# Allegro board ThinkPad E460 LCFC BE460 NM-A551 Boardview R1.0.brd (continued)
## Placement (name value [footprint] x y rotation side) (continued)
IT1  Test_Point_40MIL  [TPC40]  186.29 137.7 0 top
IT2  Test_Point_40MIL  [TPC40]  181.6 137.74 0 top
IT3  Test_Point_40MIL  [TPC40]  199.03 116.56 0 top
IT4  Test_Point_40MIL  [TPC40]  196.07 132.24 0 top
IT5  Test_Point_40MIL  [TPC40]  201.15 120.81 0 top
IT6  Test_Point_40MIL  [TPC40]  194.56 112.7 0 top
IT7  Test_Point_40MIL  [TPC40]  193.03 112.7 0 top
IT8  Test_Point_40MIL  [TPC40]  172.32 123.86 0 top
J1  SHORT PADS  [SHORTPADS]  267.95 149.19 0 top
J5  -  [JUMP_43X118]  221.34 133.04 270 top
J6  -  [JUMP_43X118]  215.37 133.04 270 top
JBATT1  FOX_GS73071-10272-M-7H  [FOX_GS73071-10272-M-7H_7P-T]  255.2 122.55 0 bottom
JC1  -  [JUMP_43X79]  144.02 158.5 0 top
JC2  -  [JUMP_43X118]  88.87 148.48 90 top
JCMOS1  SHORT PADS  [SHORTPADS]  126.61 138.1 0 bottom
JCP  ACES_50506-01201-AT1  [ACES_50506-01201-AT1_12P]  117.66 62.9 180 top
JCR  ACES_51530-01401-W01  [ACES_51530-01401-W01_14P-T]  164.45 54.72 0 top
JDIMM1  LCN_DAN06-K4406-0102  [LCN_DAN06-K4406-0102_204P]  163.55 90.35 90 bottom
JDIMM2  LCN_DAN06-K4406-0103  [LCN_DAN06-K4406-0103_204P]  150.35 90.35 270 bottom
JFAN  DRAPH_WS32050-S0471-HF  [DRAPH_WS32050-S0471-HF_5P-T]  46.2 48.31 180 bottom
JFPB  ACES_88514-0060N-071  [ACES_88514-0060N-071_6P-T]  175.96 76.54 180 top
JHDD  HIGHS_SA2S0226-3201H  [HIGHS_SA2S0226-3201H_22P]  225.57 75.7 180 bottom
JHDMI  CONCR_099ATAC19NBLCNF  [CONCR_099ATAC19NBLCNF_19P]  289.85 62 270 bottom
JKB  JAE_FL10F032HA2R3000  [JAE_FL10F032HA2R3000_32P]  147.2 71.75 0 top
JLCD  I-PEX_20525-030E-02  [I-PEX_20525-030E-02_30P-T]  58.36 112.46 315 top
JLINK  DRAPH_PJSS0296-MB21H  [DRAPH_PJSS0296-MB21H_29P-T]  285.3 121.47 90 bottom
JLOGO  TE_2041180-2  [TE_2041180-2_2P-T]  280.79 24.59 180 top
JME1  SHORT PADS  [SHORTPADS]  126.61 136.83 0 bottom
JRJ451  SINGA_2RJ3089-108211F  [SINGA_2RJ3089-108211F_12P]  288.38 82.57 90 bottom
JRTC  TE_2041180-2  [TE_2041180-2_2P-T]  234.32 170.1 0 bottom
JSPK  TYCO_2041180-4  [TYCO_2041180-4_4P-T]  240.28 98.4 0 bottom
JTOUCH1  ACES_50463-0104A-P01  [ACES_50463-0104A-P01_10P-T]  251.5 155.63 0 top
JTP  JAE_FL10F012HA1R3000  [JAE_FL10F012HA1R3000_12P]  147.2 60.75 180 top
JU3AC  HIGHS_FC5AF261-1151H  [HIGHS_FC5AF261-1151H_26P]  128.66 56.61 180 top
JUSB1  SUYIN_020053GR009M283ZL  [SUYIN_020053GR009M283ZL_9P]  285.59 29.5 270 bottom
JUSB2  SUYIN_020053GR009M283ZL  [SUYIN_020053GR009M283ZL_9P]  285.59 7.5 270 bottom
JV1  -  [JUMP_43X79]  49.87 127.18 0 bottom
JV3  -  [JUMP_43X39]  71.13 161.58 180 top
JWLBT  TE_2199230-8  [TE_2199230-8_75P]  268.95 162.77 180 bottom
L1  EXC24CH900U_4P  [PANAS_EXC24CH900U_4P]  281.17 58.85 270 top
L2  EXC24CH900U_4P  [PANAS_EXC24CH900U_4P]  282.44 60.75 270 top
L3  EXC24CH900U_4P  [PANAS_EXC24CH900U_4P]  282.31 62.78 270 top
L4  EXC24CH900U_4P  [PANAS_EXC24CH900U_4P]  281.17 57.07 270 top
L5  EXC24CH900U_4P  [PANAS_EXC24CH900U_4P]  59.43 125.52 315 bottom
L6  EXC24CH900U_4P  [PANAS_EXC24CH900U_4P]  137.28 64.05 180 top
L9  EXC24CH900U_4P  [PANAS_EXC24CH900U_4P]  280.03 33.07 90 bottom
L10  EXC24CH900U_4P  [PANAS_EXC24CH900U_4P]  280.03 34.84 90 bottom
L11  EXC24CH900U_4P  [PANAS_EXC24CH900U_4P]  283.2 41.19 180 top
L12  EXC24CH900U_4P  [PANAS_EXC24CH900U_4P]  279.9 13.76 90 bottom
L13  EXC24CH900U_4P  [PANAS_EXC24CH900U_4P]  279.9 15.41 90 bottom
L14  EXC24CH900U_4P  [PANAS_EXC24CH900U_4P]  278.76 12.62 270 top
L15  EXC24CH900U_4P  [PANAS_EXC24CH900U_4P]  277.74 116.63 270 top
L16  EXC24CH900U_4P  [PANAS_EXC24CH900U_4P]  274.69 115.11 270 top
L17  EXC24CH900U_4P  [PANAS_EXC24CH900U_4P]  135.63 63.8 180 top
L18  EXC24CH900U_4P  [PANAS_EXC24CH900U_4P]  130.24 62.94 270 top
L19  EXC24CH900U_4P  [PANAS_EXC24CH900U_4P]  242.18 153.59 180 top
L20  EXC24CH900U_4P  [PANAS_EXC24CH900U_4P]  274.19 122.47 180 top
LC1  0_0805_5%  [R0805_SHORT]  84.55 130.55 90 top
LC2  0_0805_5%  [R0805_SHORT]  109.34 133.23 270 top
LC3  0_0805_5%  [R0805_SHORT]  83.61 131.57 0 bottom
LC4  0_0805_5%  [R0805_SHORT]  82.76 126.03 0 top
LC5  0_0805_5%  [R0805_SHORT]  82.76 128.06 0 top
LE1  BLM18PG121SN1D_2P  [MURAT_BLM18PG121SN1D_2P]  199.84 119.54 180 top
LE2  BLM18PG121SN1D_2P  [MURAT_BLM18PG121SN1D_2P]  198.64 120.81 0 top
LL1  4.7UH_FLF3215T-4R7M_20%  [TDK_FLF3215T-4R7M_2P]  254.16 87.28 0 bottom
LV3  BLM18PG221SN1D_2P  [MURAT_BLM18PG221SN1D_2P]  43.82 173.2 270 bottom
LV4  BLM18PG121SN1D_2P  [MURAT_BLM18PG121SN1D_2P]  42.65 170.69 270 top
LV5  BLM18PG121SN1D_2P  [MURAT_BLM18PG121SN1D_2P]  50.25 130.54 90 bottom
NOREF  -  []  192.07 77.63 0 top
NOREF#2  -  []  180.04 3.42 0 top
NOREF#3  -  []  212.11 124.71 0 top
NOREF#4  -  [unnamed#2]  10.79 131.08 0 top
NOREF#5  -  []  192.93 114.91 0 top
NOREF#6  -  []  211.37 84.37 0 top
NOREF#7  -  []  90.74 54.21 0 top
NOREF#8  -  []  160.53 61.96 180 bottom
NOREF#9  -  []  154.83 60.22 180 bottom
NOREF#10  -  []  124.57 61.42 180 bottom
PC1  1U_0603_25V7K  [C_0603]  240.47 129.17 180 bottom
PC2  680P_0402_50V7-K  [C_0402]  276.64 107.78 90 top
PC3  0.1U_0402_6.3V  [C_0402]  275.72 107.78 90 top
PC4  1000P_0402_50V7-K  [C_0402]  278.11 107.8 90 bottom
PC5  100P_0402_50V8-J  [C_0402]  279.03 107.8 90 bottom
PC6  100P_0402_50V8J  [C_0402]  275.77 102.39 270 bottom
PC7  1000P_0402_50V7-K  [C_0402]  274.89 102.39 270 bottom
PC8  0.1U_0603_16V7K  [C_0603]  222.21 169.63 270 top
PC9  1000P_0402_50V  [C_0402]  264.84 109.52 0 bottom
PC10  0.01U_0402_25V  [C_0402]  260.28 109.25 180 bottom
PC101  470P_0402_50V  [C_0402]  273.95 108.77 180 bottom
PC102  0.022U_0402_25V  [C_0402]  272.42 103.64 180 bottom
PC103  10U_0805_25V6-K  [C_0805]  265.56 102.27 0 bottom
PC104  10U_0805_25V6-K  [C_0805]  263.76 102.22 180 bottom
PC105  0.1U_0402_25V7K  [C_0402]  222.1 105.32 180 bottom
PC106  0.1U_0402_25V7K  [C_0402]  223 104.82 0 bottom
PC107  1U_0603_25V7-K  [C_0603]  221.29 104.02 180 bottom
PC108  0.01U_0603_50V7K  [C_0603]  247.71 101.51 0 top
PC109  100P_0402_50V8-J  [C_0402]  223.86 107.09 270 bottom
PC110  2200P_0402_25V7-K  [C_0402]  233.05 119.29 180 bottom
PC111  47P_0402_50V8-J  [C_0402]  232.14 120.17 0 bottom
PC112  68P_0402_50V8-J  [C_0402]  232.14 121.04 0 bottom
PC113  10U_0805_25V6K  [C_0805]  228.66 118.7 180 bottom
PC114  10U_0805_25V6K  [C_0805]  228.66 120.43 180 bottom
PC115  1U_0603_25V  [C_0603]  222.84 108.92 0 bottom
PC116  4.7U_0603_10V6-M  [C_0603]  224.06 112.53 0 bottom
PC117  0.1U_0402_25V7K  [C_0402]  217.02 106.18 90 bottom
PC118  0.047U_0603_25V  [C_0603]  224.31 110.14 0 bottom
PC119  10U_0805_25V6-K  [C_0805]  256.83 102.17 90 bottom
PC120  10U_0805_25V6-K  [C_0805]  254.24 102.19 90 bottom
PC121  680P_0402_50V7K  [C_0402]  234.12 117.18 90 top
PC122  0.1U_0402_25V7K  [C_0402]  221.47 117 270 bottom
PC123  0.1U_0402_25V7K  [C_0402]  218.12 116.97 270 bottom
PC124  0.1U_0402_25V7K  [C_0402]  219.69 117.81 180 bottom
PC125  100P_0402_50V8J  [C_0402]  214.28 105.8 90 bottom
PC126  100P_0402_50V8J  [C_0402]  213.62 109.38 0 bottom
PC127  100P_0402_50V8J  [C_0402]  212.76 109.4 90 bottom
PC128  0.1U_0402_25V6  [C_0402]  223.22 116.44 180 bottom
PC201  0.1U_0402_25V6-K  [C_0402]  210.52 168.1 180 bottom
PC202  10U_0805_25V6-K  [C_0805]  210.5 170.29 180 bottom
PC203  0.1U_0603_25V7-M  [C_0603]  212.07 161.93 90 top
PC204  22U_0805_6.3V6-M  [C_0805]  217.61 155.94 0 bottom
PC205  22U_0805_6.3V6-M  [C_0805]  217.13 154.16 0 bottom
PC206  22U_0805_6.3V6-M  [C_0805]  211.82 152.1 180 bottom
PC207  22U_0805_6.3V6-M  [C_0805]  211.74 154.11 180 bottom
PC208  4.7U_0603_6.3V6-K  [C_0603]  216.57 167.72 0 bottom
PC209  680P_0402_50V7K  [C_0402]  208.64 165.56 270 bottom
PC210  2200P_0402_25V7-K  [C_0402]  217.02 152.79 0 bottom
PC211  0.1U_0402_25V6  [C_0402]  217 151.87 0 bottom
PC212  0.01U_0402_25V7-K  [C_0402]  216.67 165.79 0 bottom
PC213  0.1U_0402_25V6-K  [C_0402]  217.94 164.4 180 bottom
PC214  10U_0805_25V6-K  [C_0805]  198.29 174.09 270 bottom
PC215  0.1U_0402_25V6-K  [C_0402]  199.94 174.67 90 bottom
PC216  10U_0805_25V6-K  [C_0805]  198.29 174.09 270 top
PC217  0.1U_0603_25V7-M  [C_0603]  200.96 167.12 90 top
PC218  1U_0603_25V6M  [C_0603]  205.06 175.35 270 bottom
PC219  22U_0805_6.3V6-M  [C_0805]  203.44 157.74 0 bottom
PC220  22U_0805_6.3V6-M  [C_0805]  203.44 157.74 0 top
PC221  22U_0805_6.3V6-M  [C_0805]  198.56 160.64 180 bottom
PC222  22U_0805_6.3V6-M  [C_0805]  203.44 159.47 0 top
PC223  22U_0805_6.3V6-M  [C_0805]  203.44 159.47 0 bottom
PC224  22U_0805_6.3V6-M  [C_0805]  198.56 160.64 180 top
PC225  4.7U_0603_6.3V6-K  [C_0603]  202.55 175.35 0 bottom
PC226  680P_0402_50V7K  [C_0402]  197.7 168.9 270 bottom
PC227  2200P_0402_25V7-K  [C_0402]  204.38 156.45 0 bottom
PC228  0.1U_0402_25V6  [C_0402]  198.97 159.32 180 bottom
PC229  6800P_0402_25V7-K  [C_0402]  204.38 172.14 270 bottom
PC230  47P_0402_50V8-J  [C_0402]  210.5 168.97 180 bottom
PC231  47P_0402_50V8-J  [C_0402]  200.83 174.67 90 bottom
PC301  10U_0603_6.3V6M  [C_0603]  177.58 169.25 270 top
PC302  10U_0805_25V6-K  [C_0805]  170.95 167.68 270 top
PC303  10U_0805_25V6-K  [C_0805]  171.59 167.55 270 bottom
PC304  0.1U_0402_25V6  [C_0402]  171.16 169.13 90 top
PC305  47P_0402_50V8-J  [C_0402]  169.61 166.9 270 top
PC306  68P_0402_50V8J  [C_0402]  170.23 166.91 270 bottom
PC307  2200P_0402_25V  [C_0402]  171.15 169.14 90 bottom
PC308  10U_0603_6.3V6M  [C_0603]  179.08 167.01 270 top
PC309  0.1U_0402_6.3V7-K  [C_0402]  177.45 166.94 180 top
PC310  0.22U_0603_25V7K  [C_0603]  177.53 173.15 180 top
PC311  330U_D2_2V_R9M  [C_D2]  159.29 166.3 0 bottom
PC312  2200P_0402_25V7-K  [C_0402]  157.8 163.55 270 bottom
PC313  0.1U_0402_25V6  [C_0402]  158.68 163.55 270 bottom
PC314  470P_0402_50V7K  [C_0402]  181.67 165.82 90 top
PC315  0.033U_0402_16V7K  [C_0402]  180.8 166.37 270 top
PC316  1U_0402_10VA-K  [C_0402]  181.13 173.29 0 top
PC317  680P_0402_50V7K  [C_0402]  168.31 175.31 270 top
PC318  0.1U_0402_6.3V7-K  [C_0402]  184.33 168.59 0 top
PC319  0.1U_0402_16V  [C_0402]  184.33 170.36 0 top
PC401  0.01U_0402_25V7-K  [C_0402]  70.06 54.24 270 bottom
PC402  1U_0402_6.3V6-K  [C_0402]  68.13 53.98 0 bottom
PC403  0.1U_0402_6.3V6-K  [C_0402]  55.38 60.81 0 bottom
PC404  1000P_0402_25V7-K  [C_0402]  60.28 51.04 270 bottom
PC405  0.033U_0402_25V7K  [C_0402]  58.58 56.83 270 bottom
PC406  1000P_0402_25V7-K  [C_0402]  59.39 51.85 270 bottom
PC407  3300P_0402_50V7-K  [C_0402]  60.31 51.87 90 bottom
PC408  0.1U_0402_25V6-K  [C_0402]  63.89 51.82 270 bottom
PC409  15P_0402_50V8-J  [C_0402]  58.5 53.65 0 bottom
PC410  1500P_0402_50V7-K  [C_0402]  58.5 52.76 0 bottom
PC411  270P_0402_50V7-M  [C_0402]  57.69 57.74 0 bottom
PC412  1000P_0402_50V7-K  [C_0402]  57.84 55.07 0 bottom
PC413  1000P_0402_25V7-K  [C_0402]  69.53 63.15 180 bottom
PC414  0.1U_0402_25V6-K  [C_0402]  69.91 56.75 90 bottom
PC415  3300P_0402_50V7-K  [C_0402]  69.45 61.88 180 bottom
PC416  470P_0402_50V8-J  [C_0402]  71.66 62.57 180 bottom
PC417  0.1U_0402_16V7-K  [C_0402]  70.9 57.18 270 bottom
PC418  100P_0402_50V7-K  [C_0402]  71.69 58.02 180 top
PC419  1000P_0402_25V7-K  [C_0402]  71.66 58.02 180 bottom
PC420  2200P_0402_25V7-K  [C_0402]  71.63 59.95 180 bottom
PC421  470P_0402_50V8-J  [C_0402]  73.24 60.81 180 bottom
PC422  33P_0402_50V8-J  [C_0402]  70.77 60.81 270 top
PC423  1000P_0402_25V7-K  [C_0402]  68.89 66.12 270 bottom
PC424  0.1U_0402_25V6-K  [C_0402]  70.97 55.3 270 bottom
PC425  1000P_0402_25V7-K  [C_0402]  67.14 67.06 0 bottom
PC426  3300P_0402_50V7-K  [C_0402]  67.16 66.15 270 bottom
PC427  15P_0402_50V8-J  [C_0402]  64.5 65.16 270 bottom
PC428  0.01U_0402_25V6-K  [C_0402]  65.36 65.16 270 bottom
PC429  0.018U_0402_50V7-J  [C_0402]  61.83 64.27 0 bottom
PC430  270P_0402_50V7-M  [C_0402]  60.97 64.85 270 bottom
PC431  1000P_0402_50V7-K  [C_0402]  63.61 65.16 270 bottom
PC432  10U_0805_25V6-K  [C_0805]  72.73 66.96 270 bottom
PC433  10U_0805_25V6-K  [C_0805]  74.45 66.96 270 top
PC434  10U_0805_25V6-K  [C_0805]  72.73 66.96 270 top
PC435  10U_0805_25V6-K  [C_0805]  74.45 66.96 270 bottom
PC436  0.1U_0402_25V6  [C_0402]  75.6 70.57 0 bottom
PC437  2200P_0402_25V7-K  [C_0402]  75.6 69.7 0 bottom
PC438  47P_0402_50V8-J  [C_0402]  71.36 66.68 270 bottom
PC439  3300P_0402_50V7-K  [C_0402]  61.83 65.13 0 bottom
PC440  1000P_0402_50V7-K  [C_0402]  57.72 56.85 270 bottom
PC441  1U_0402_6.3V6-K  [C_0402]  58.49 61.9 180 bottom
PC442  0.22U_0603_25V7-K  [C_0603]  68.18 73.16 270 bottom
PC443  330U_D2_2VM_R9M  [C_D2]  75.14 88.17 180 bottom
PC444  1U_0402_10V  [C_0402]  64.29 69.07 180 bottom
PC445  680P_0402_50V7K  [C_0402]  65.54 75.32 90 top
PC446  10U_0805_25V6-K  [C_0805]  80.65 59.98 0 bottom
PC447  10U_0805_25V6-K  [C_0805]  76.92 58.33 180 bottom
PC448  10U_0805_25V6-K  [C_0805]  77.65 60.08 180 bottom
PC449  10U_0805_25V6-K  [C_0805]  77.65 61.88 180 bottom
PC450  0.1U_0402_25V6  [C_0402]  76.69 57.03 180 bottom
PC451  2200P_0402_25V7-K  [C_0402]  76.74 63.25 180 bottom
PC452  47P_0402_50V8-J  [C_0402]  76.74 64.17 180 bottom
PC453  0.22U_0603_25V7-K  [C_0603]  83.95 54.87 180 top
PC454  330U_D2_2VM_R9M  [C_D2]  95.99 66.58 270 bottom
PC455  1U_0402_10V  [C_0402]  84.72 48.98 0 top
PC456  680P_0402_50V7K  [C_0402]  97.29 50.55 90 bottom
PC457  10U_0805_25V6-K  [C_0805]  74.02 97.49 270 bottom
PC458  10U_0805_25V6-K  [C_0805]  74.02 97.49 270 top
PC459  0.1U_0402_25V6  [C_0402]  69.91 96.68 270 bottom
PC460  2200P_0402_25V7-K  [C_0402]  70.8 96.68 270 bottom
PC461  47P_0402_50V8-J  [C_0402]  68.94 96.63 180 bottom
PC462  0.22U_0603_25V7-K  [C_0603]  71.63 100.72 90 bottom
PC463  1U_0402_10V  [C_0402]  77.07 98.53 270 bottom
PC464  680P_0402_50V7K  [C_0402]  66.43 100.87 180 top
PC465  22U_0603_6.3V6M  [C_0603]  97.81 117.32 270 top
PC466  22U_0603_6.3V6M  [C_0603]  69.12 87.61 0 top
PC467  22U_0603_6.3V6M  [C_0603]  96.61 118.31 90 top
PC468  22U_0603_6.3V6M  [C_0603]  95.1 123.54 270 top
PC469  22U_0603_6.3V6M  [C_0603]  99.04 117.32 270 top
PC470  22U_0603_6.3V6M  [C_0603]  97.64 123.54 270 top
PC471  22U_0603_6.3V6M  [C_0603]  93.45 113.51 90 top
PC472  22U_0603_6.3V6M  [C_0603]  94.72 113.51 90 top
PC473  22U_0603_6.3V6M  [C_0603]  69.15 88.83 0 top
PC474  22U_0603_6.3V6M  [C_0603]  94.18 118.31 90 top
PC475  22U_0603_6.3V6M  [C_0603]  99.3 113.38 90 top
PC476  22U_0603_6.3V6M  [C_0603]  98.53 118.33 90 top
PC477  22U_0603_6.3V6M  [C_0603]  99.61 120.94 180 top
PC478  22U_0603_6.3V6M  [C_0603]  98.91 123.54 270 top
PC479  22U_0603_6.3V6M  [C_0603]  94.02 111.03 180 top
PC480  22U_0603_6.3V6M  [C_0603]  69.15 90.05 0 top
PC481  22U_0603_6.3V6M  [C_0603]  69.15 91.29 0 top
PC482  22U_0603_6.3V6M  [C_0603]  92.95 118.08 90 top
PC483  22U_0603_6.3V6M  [C_0603]  95.04 120.81 0 top
PC484  22U_0603_6.3V6M  [C_0603]  96.37 123.54 270 top
PC485  22U_0603_6.3V6M  [C_0603]  95.99 113.51 90 top
PC486  22U_0603_6.3V6M  [C_0603]  97.26 113.51 90 top
PC487  22U_0603_6.3V6M  [C_0603]  95.4 118.31 90 top
PC488  22U_0603_6.3V6M  [C_0603]  106.09 109.65 270 top
PC489  22U_0603_6.3V6M  [C_0603]  110.18 109.6 270 top
PC490  22U_0603_6.3V6M  [C_0603]  100.63 82.33 0 top
PC491  22U_0603_6.3V6M  [C_0603]  100.63 79.79 0 top
PC492  22U_0603_6.3V6M  [C_0603]  104.57 85.63 0 top
PC493  22U_0603_6.3V6M  [C_0603]  103.23 85.82 270 top
PC494  22U_0603_6.3V6M  [C_0603]  110.99 104.85 270 top
PC495  22U_0603_6.3V6M  [C_0603]  109.57 104.85 270 top
PC496  22U_0603_6.3V6M  [C_0603]  100.63 81.06 0 top
PC497  22U_0603_6.3V6M  [C_0603]  105.96 80.93 180 top
PC498  22U_0603_6.3V6M  [C_0603]  109.13 105.84 90 top
PC499  22U_0603_6.3V6M  [C_0603]  104.57 84.23 0 top
PC500  22U_0603_6.3V6M  [C_0603]  111.4 109.6 270 top
PC501  22U_0603_6.3V6M  [C_0603]  107.86 105.84 90 top
PC502  22U_0603_6.3V6M  [C_0603]  108.15 102 270 top
PC503  22U_0603_6.3V6M  [C_0603]  105.96 78.39 180 top
PC504  22U_0603_6.3V6M  [C_0603]  105.96 79.66 180 top
PC505  22U_0603_6.3V6M  [C_0603]  100.63 78.52 0 top
PC506  22U_0603_6.3V6M  [C_0603]  104.84 109.65 270 top
PC507  22U_0603_6.3V6M  [C_0603]  104.58 87.04 0 top
PC508  22U_0603_6.3V6M  [C_0603]  110.89 105.84 90 top
PC509  22U_0603_6.3V6M  [C_0603]  106.93 102 270 top
PC510  22U_0603_6.3V6M  [C_0603]  108.12 104.85 270 top
PC511  22U_0603_6.3V6M  [C_0603]  106.22 105.91 180 top
PC512  22U_0603_6.3V6M  [C_0603]  106.22 103.45 180 top
PC513  22U_0603_6.3V6M  [C_0603]  75.14 104.07 90 bottom
PC514  22U_0603_6.3V6M  [C_0603]  106.7 123.62 270 top
PC515  22U_0603_6.3V6M  [C_0603]  104.26 123.62 270 top
PC516  22U_0603_6.3V6M  [C_0603]  75.17 111.41 270 bottom
PC517  22U_0603_6.3V6M  [C_0603]  76.38 104.07 90 bottom
PC518  22U_0603_6.3V6M  [C_0603]  76.44 104.11 90 top
PC519  22U_0603_6.3V6M  [C_0603]  111.57 123.62 270 top
PC520  22U_0603_6.3V6M  [C_0603]  107.56 119.5 90 top
PC521  22U_0603_6.3V6M  [C_0603]  106.34 119.5 90 top
PC522  22U_0603_6.3V6M  [C_0603]  76.36 111.41 270 bottom
PC523  22U_0603_6.3V6M  [C_0603]  75.17 104.11 90 top
PC524  22U_0603_6.3V6M  [C_0603]  107.92 123.62 270 top
PC525  33U_D2_25VM_R40M  [C_D2]  77.63 73.39 0 bottom
PC526  33U_D2_25VM_R40M  [C_D2]  75.65 92.87 180 bottom
PC527  33U_D2_25VM_R40M  [C_D2]  82.4 68.82 270 bottom
PC528  33U_D2_25VM_R40M  [C_D2]  214.42 124.56 180 bottom
PC601  0.1U_0402_25V6  [C_0402]  122.23 170.52 180 bottom
PC602  47P_0402_50V8-J  [C_0402]  110.29 159.42 270 top
PC603  2200P_0402_50V7K  [C_0402]  110.29 159.42 270 bottom
PC604  1U_0402_10V  [C_0402]  111.31 170.54 180 bottom
PC605  1U_0402_10V  [C_0402]  111.28 171.43 180 bottom
PC606  0.1U_0402_25V6  [C_0402]  110.6 162.77 0 bottom
PC607  10U_0805_25V6K  [C_0805]  108.8 159.67 270 top
PC608  0.22U_0603_25V  [C_0603]  121.32 164.9 90 bottom
PC609  100P_0402_50V8-J  [C_0402]  114.43 165.06 90 bottom
PC610  150P_0402_50V8-J  [C_0402]  113.54 165.06 90 bottom
PC611  10U_0805_25V6K  [C_0805]  108.8 159.67 270 bottom
PC612  0.22U_0603_25V  [C_0603]  110.27 167.55 90 bottom
PC613  330U_D2_2VM_R9M  [C_D2]  78.47 166.12 180 bottom
PC614  330U_D2_2VM_R9M  [C_D2]  81.49 161.37 180 bottom
PC615  0.1U_0402_25V6  [C_0402]  82.61 158.5 270 bottom
PC616  680P_0402_50V  [C_0402]  91.88 163.41 90 top
PC617  470P_0402_50V  [C_0402]  116.24 165.08 270 bottom
PC618  0.22U_0603_25V7-K  [C_0603]  110.75 174.84 270 bottom
PC619  330P_0402_50V7-K  [C_0402]  118.22 163.35 90 bottom
PC620  680P_0402_50V7-K  [C_0402]  113.57 165.06 180 top
PC621  330P_0402_50V7-K  [C_0402]  118.29 165.84 180 bottom
PC622  1000P_0402_25V7-K  [C_0402]  117.33 164.27 270 bottom
PC623  47P_0402_50V8-J  [C_0402]  100.51 169.02 180 bottom
PC624  2200P_0402_50V7K  [C_0402]  100.57 168.15 180 bottom
PC625  0.1U_0402_25V6  [C_0402]  105.06 170.49 0 bottom
PC626  10U_0805_25V6K  [C_0805]  105.32 169.17 0 top
PC627  10U_0805_25V6K  [C_0805]  105.32 169.17 0 bottom
PC628  0.22U_0603_25V  [C_0603]  122.77 164.88 90 bottom
PC629  330U_D2_2VM_R9M  [C_D2]  74.28 170.9 180 bottom
PC630  330U_D2_2VM_R9M  [C_D2]  74.28 170.9 180 top
PC631  0.1U_0402_25V6  [C_0402]  81.19 158.5 270 bottom
PC632  680P_0402_50V7K  [C_0402]  89.21 168.76 270 top
PC633  0.1U_0402_25V7K  [C_0402]  120.05 165.89 270 bottom
PC634  82N_0402_50V  [C_0402]  120.43 163.2 180 bottom
PC635  330P_0402_50V  [C_0402]  119.16 165.87 270 top
PC636  0.1U_0402_25V  [C_0402]  124.59 167.72 90 bottom
PC637  0.1U_0402_25V6  [C_0402]  118.17 162.31 0 bottom
PC701  0.1U_0402_16V7-K  [C_0402]  148.5 166.4 270 bottom
PC702  0.1U_0402_6.3V7-K  [C_0402]  149.84 165.74 90 bottom
PC703  0.01U_0402_25V7-K  [C_0402]  153.17 168.74 270 bottom
PC704  0.1U_0603_25V7K  [C_0603]  143.64 170.36 90 top
PC705  2.2U_0603_10V6-K  [C_0603]  154.77 170.64 180 bottom
PC706  68P_0402_50V8J  [C_0402]  153.42 172.57 0 bottom
PC707  10U_0805_25V6-K  [C_0805]  151.77 174.94 180 top
PC708  10U_0805_25V6-K  [C_0805]  151.77 174.94 180 bottom
PC709  2200P_0402_25V7-K  [C_0402]  153.42 171.71 0 top
PC710  0.1U_0402_25V6  [C_0402]  153.42 172.57 0 top
PC711  22U_0805_6.3V6-M  [C_0805]  141.66 165.06 270 top
PC712  22U_0805_6.3V6-M  [C_0805]  143.39 165.06 270 bottom
PC713  22U_0805_6.3V6-M  [C_0805]  141.66 165.06 270 bottom
PC714  47P_0402_50V8-J  [C_0402]  153.42 171.71 0 bottom
PC715  22U_0805_6.3V6-M  [C_0805]  143.39 165.06 270 top
PC716  2200P_0402_25V7-K  [C_0402]  144.7 164.89 270 bottom
PC717  0.1U_0402_25V6  [C_0402]  140.35 164.46 270 bottom
PC718  680P_0402_50V7K  [C_0402]  145.07 174.3 0 top
PC801  10U_0603_10V  [C_0603]  192.37 171.14 0 bottom
PC802  10U_0603_10V  [C_0603]  192.37 172.35 0 bottom
PC803  0.22U_0402_10V6-K  [C_0402]  185.97 175.51 0 bottom
PC804  680P_0402_50V  [C_0402]  190.17 171.04 270 top
PC805  22P_0402_50V  [C_0402]  193.06 174.26 180 bottom
PC806  22U_0805_6.3VAM  [C_0805]  191.47 164.26 270 bottom
PC807  22U_0805_6.3VAM  [C_0805]  189.73 164.24 270 bottom
PC808  0.1U_0402_25V6  [C_0402]  188.38 163.59 270 bottom
PD1  RB751V-40  [RB751V-40_SOD323-2]  231.38 129.47 180 bottom
PD2  1SS355  [RB751V-40_SOD323-2]  233.05 125.74 180 bottom
PD3  RB751V-40  [RB751V-40_SOD323-2]  231.38 127.72 180 bottom
PD4  -  [RB751V-40_SOD323-2]  277.78 104.15 90 top
PD5  -  [AZ5425-01F_DFN1006P2E2]  279.03 107.68 90 top
PD6  RB751V-40  [RB751V-40_SOD323-2]  218.15 172.23 0 bottom
PD7  -  [PESD5V0U2BT_SOT23-3]  253.47 122.36 90 top
PD101  RB751V-40  [RB751V-40_SOD323-2]  271.63 109.79 0 top
PD102  RB751V-40  [RB751V-40_SOD323-2]  227.13 104.05 180 bottom
PD103  RB751V-40  [RB751V-40_SOD323-2]  227.54 105.75 90 bottom
PD801  RB751V-40  [RB751V-40_SOD323-2]  186.08 173.21 90 top
PF1  7A_32V_0437007.WR  [F_0437007PWR]  278.39 106.15 0 bottom
PF2  12A_32V_0501012.WRS  [F_0437007PWR]  262.21 114.05 180 bottom
PJ201  -  [JUMP_43X79]  212.63 170.82 90 bottom
PJ202  -  [JUMP_43X118]  214.43 150.88 90 bottom
PJ203  -  [JUMP_43X79]  196.82 173.76 180 bottom
PJ204  -  [JUMP_43X118]  201.89 155.15 90 bottom
PJ301  -  [JUMP_43X118]  155.52 165.03 0 bottom
PJ302  -  [JUMP_43X118]  155.02 165.3 0 top
PJ303  -  [JUMP_43X39]  177.43 164.83 90 top
PJ304  -  [JUMP_43X79]  173.07 168.11 0 bottom
PJ701  -  [JUMP_43X79]  153 174.48 0 bottom
PJ702  -  [JUMP_43X118]  138.01 165.31 0 top
PJ703  -  [JUMP_43X118]  138.01 165.31 0 bottom
PJ801  -  [JUMP_43X39]  193.52 168.62 270 bottom
PJ802  -  [JUMP_43X39]  186.2 163.79 0 bottom
PL1  MURATA BLM18KG300TN1D  [TDK_MPZ1608S300AT_2P]  278.29 103.87 180 bottom
PL2  MURATA BLM18KG300TN1D  [TDK_MPZ1608S300AT_2P]  278.29 102.67 180 bottom
PL3  MURATA BLM18KG300TN1D  [TDK_MPZ1608S300AT_2P]  260.92 111.56 180 bottom
PL4  MURATA BLM18KG300TN1D  [TDK_MPZ1608S300AT_2P]  260.92 110.32 180 bottom
PL101  1UH_PCMB053T-1R0MS_20%  [CYNTE_PCMB053T-1R0MS_2P]  265.89 106.23 180 bottom
PL102  4.7UH_PCMB104T-4R7MS  [CYNTE_PCMB104T-100MS_2P]  231.99 109.1 0 bottom
PL201  2.2UH_PCMB063T-2R2MS_8A_20%  [CYNTE_PCMB063T-2R2MS_2P]  213.04 162.8 270 bottom
PL202  2.2UH_PCMB063T-2R2MS_8A_20%  [CYNTE_PCMB063T-2R2MS_2P]  202.19 168.08 270 bottom
PL301  1UH_PCMC063T-1R0MN_+-20%  [CYNTE_PCMB063T-1R0MS_2P]  158.78 172.44 0 bottom
PL401  BLM18KG300TN1D  [TDK_MPZ1608S300AT_2P]  76.74 66.89 0 bottom
PL402  BLM18KG300TN1D  [TDK_MPZ1608S300AT_2P]  76.77 68.26 0 bottom
PL403  CMLE064T-R15MS0R725-88(0.72mohm+/-5%)  [CYNTE_CMLE064T-R15MS0R66788_2P]  73.21 77.1 90 bottom
PL404  BLM18KG300TN1D  [TDK_MPZ1608S300AT_2P]  77.86 63.84 90 bottom
PL405  BLM18KG300TN1D  [TDK_MPZ1608S300AT_2P]  79.31 63.84 90 bottom
PL406  CMLE064T-R15MS0R725-88(0.72mohm+/-5%)  [CYNTE_CMLE064T-R15MS0R66788_2P]  89.72 60.31 90 bottom
PL407  BLM18KG300TN1D  [TDK_MPZ1608S300AT_2P]  76.03 97.11 270 bottom
PL408  0.47UH_PCMB063T-R47MS3R675_18A_20%(DCR+/-5%)  [CYNTE_CMLE064T-R15MS0R66788_2P]  65.89 106.23 0 bottom
PL601  MURATA BLM18KG300TN1D  [TDK_MPZ1608S300AT_2P]  110.22 161.63 0 bottom
PL602  MURATA BLM18KG300TN1D  [TDK_MPZ1608S300AT_2P]  110.22 160.43 0 bottom
PL603  .24UH 20% PCME063T-R24MS1R145 35A  [CYNTE_PCMB063T-1R0MS_2P]  91.37 161.47 180 bottom
PL604  .24UH 20% PCME063T-R24MS1R145 35A  [CYNTE_PCMB063T-1R0MS_2P]  88.97 169.75 180 bottom
PL701  1UH_PCMC063T-1R0MN_+-20%  [CYNTE_PCMB063T-1R0MS_2P]  143.21 174.17 270 bottom
PL801  1UH_PH041H-1R0MS_20%  [CYNTE_PH041H-1R0MS_2P]  189.27 169.35 270 bottom
PQ1  -  [MMBT3906_SOT23-3]  236.13 126.75 0 bottom
PQ2  -  [MMBT3904_SOT23-3]  240.32 125.08 180 bottom
PQ3  2N7002WT1G  [2N7002KW_SOT323-3]  235.06 129.5 90 bottom
PQ4  2N7002KDWH 2N SOT363-6  [2N7002BKS_SOT363-6]  275.62 105.26 180 top
PQ101  AON7466  [SIS406DN-T1-GE3_PAK1212-8-5]  273.34 105.47 90 bottom
PQ102  AON7466  [SIS406DN-T1-GE3_PAK1212-8-5]  271.38 106.92 270 bottom
PQ103  2N7002WT1G  [2N7002KW_SOT323-3]  268.59 111.06 0 bottom
PQ104  AON7466  [SIS406DN-T1-GE3_PAK1212-8-5]  247.61 101.45 0 bottom
PQ105  2N7002WT1G  [2N7002KW_SOT323-3]  269.7 110.12 90 top
PQ106  AON7408L  [SI7326DN-T1-E3_PAK1212-8]  231.93 115.15 180 bottom
PQ107  AON7408L  [SI7326DN-T1-E3_PAK1212-8]  233.69 117.99 0 bottom
PQ201  2N7002KDWH 2N  [2N7002BKS_SOT363-6]  220.59 163.11 270 bottom
PQ301  AON7408L  [SI7326DN-T1-E3_PAK1212-8]  167.98 170.89 0 bottom
PQ302  AON7534  [SI7326DN-T1-E3_PAK1212-8]  167.34 175.24 0 bottom
PQ401  TPCA8065-H  [TPCA8065-H_PPAK56-8-5]  69.91 73.84 0 bottom
PQ402  TPCA8057-H  [TPCA8059-H_PPAK56-8-5]  62.92 74.43 90 bottom
PQ403  TPCA8057-H  [TPCA8059-H_PPAK56-8-5]  62.92 79.97 90 bottom
PQ404  TPCA8065-H  [TPCA8065-H_PPAK56-8-5]  83.67 58.22 270 bottom
PQ405  TPCA8057-H  [TPCA8059-H_PPAK56-8-5]  95.82 50.93 180 bottom
PQ406  TPCA8057-H  [TPCA8059-H_PPAK56-8-5]  89.82 50.91 180 bottom
PQ407  AON7408L  [SI7326DN-T1-E3_PAK1212-8]  67.82 101.84 0 bottom
PQ408  AON7408L  [SI7326DN-T1-E3_PAK1212-8]  63.48 99.83 90 bottom
PQ601  TPCA8065-H  [TPCA8065-H_PPAK56-8-5]  101.61 159.16 90 bottom
PQ602  TPCA8057-H  [TPCA8059-H_PPAK56-8-5]  95.31 163.28 0 bottom
PQ603  TPCA8057-H  [TPCA8059-H_PPAK56-8-5]  97.85 163.28 180 top
PQ604  TPCA8065-H  [TPCA8065-H_PPAK56-8-5]  98.43 170.24 90 bottom
PQ605  TPCA8057-H  [TPCA8059-H_PPAK56-8-5]  96.35 168.61 180 bottom
PQ606  TPCA8057-H  [TPCA8059-H_PPAK56-8-5]  93.81 168.61 0 top
PR1  100K_0402_1%  [R_0402]  233.23 127.95 0 bottom
PR2  10K_0402_1%  [R_0402]  233.79 128.81 180 bottom
PR3  750K_0402_5%  [R_0402]  233.79 129.7 180 bottom
PR4  750_0402_1%  [R_0402]  277.22 102.85 0 top
PR5  1M_0402_5%  [R_0402]  273.97 107.22 270 top
PR6  0_0402_5%  [R_0402]  279.43 104.81 270 top
PR7  10K_0402_1%  [R_0402]  279.1 105.67 90 top
PR8  1M_0402_5%  [R_0402]  273.9 105.44 270 top
PR9  16.5K_0402_1%  [R_0402]  224.19 169.7 180 top
PR10  12.7K_0402_1%  [R_0402]  225.99 170.31 270 top
PR11  47K_0402_1%  [R_0402]  225.1 170.31 270 top
PR12  20K_0402_1%  [R_0402]  227.97 168.56 270 top
PR13  0_0402_5%  [R0402_SHORT]  221.51 166.72 0 top
PR14  100_0402_1%  [R_0402]  249.18 127.03 180 bottom
PR15  100_0402_1%  [R_0402]  249.18 126.14 180 bottom
PR16  100K_0402_1%  [R_0402]  251.29 127.01 270 bottom
PR17  10K_0402_1%  [R_0402]  252.18 126.09 90 bottom
PR18  3.01K_0402_1%  [R_0402]  219.63 170.4 180 bottom
PR19  43K_0402_1%  [R_0402]  221.4 170.4 180 bottom
PR101  0.01_1206_1%  [R_1206]  258.77 100.38 180 bottom
PR102  4.7_0603_5%  [R_0603]  272.45 109.81 0 bottom
PR103  499K_0402_1%  [R_0402]  248.85 102.65 180 top
PR104  1M_0402_5%  [R_0402]  270.54 107.4 0 top
PR105  1M_0402_5%  [R_0402]  269.07 108.26 0 top
PR106  10_0402_1%  [R_0402]  222.08 106.18 90 bottom
PR107  10_0402_1%  [R_0402]  221.22 106.18 90 bottom
PR108  1K_0402_1%  [R_0402]  222.97 107.09 270 bottom
PR109  0_0402_5%  [R0402_SHORT]  266.87 111.96 270 top
PR110  10K_0402_1%  [R_0402]  266.88 109.3 90 top
PR111  4.02K_0603_1%  [R_0603]  218.95 105.65 90 bottom
PR112  4.02K_0603_1%  [R_0603]  220.15 105.65 90 bottom
PR113  432K_0402_1%  [R_0402]  216.97 104.65 180 bottom
PR114  10_1206_5%  [R_1206]  225.71 108.24 270 bottom
PR115  68K_0402_1%  [R_0402]  216.14 106.18 90 bottom
PR116  2.2_0603_5%  [R_0603]  224.31 111.34 0 bottom
PR117  0.01_1206_1%  [R_1206]  248.61 103.42 0 bottom
PR118  0_0402_5%  [R0402_SHORT]  217.9 106.22 90 bottom
PR119  4.7_0603_5%  [R_0603]  232.95 116.36 270 top
PR120  0_0402_5%  [R0402_SHORT]  213.66 112.06 0 bottom
PR121  0_0402_5%  [R0402_SHORT]  213.66 112.95 0 bottom
PR122  0_0402_5%  [R0402_SHORT]  214.27 107.56 0 bottom
PR123  0_0402_5%  [R0402_SHORT]  214.27 108.45 0 bottom
PR124  0_0402_5%  [R0402_SHORT]  213.63 110.28 0 bottom
PR125  10_0603_5%  [R_0603]  220.43 116.9 270 bottom
PR126  0_0402_5%  [R0402_SHORT]  213.66 111.17 0 bottom
PR128  10_0603_5%  [R_0603]  219.18 116.9 270 bottom
PR129  0_0402_5%  [R0402_SHORT]  223.64 114.7 180 bottom
PR130  316K_0402_1%  [R_0402]  223.81 117.76 180 bottom
PR131  18.2K_0402_1%  [R_0402]  217.18 116.77 270 bottom
PR132  100K_0402_1%  [R_0402]  223.22 115.58 180 bottom
PR201  1M_0402_5%  [R_0402]  214.03 169.7 0 bottom
PR202  0_0603_5%  [R0603_SHORT]  213.71 163.36 270 top
PR203  0_0402_5%  [R0402_SHORT]  217.04 166.67 0 bottom
PR204  4.7_0603_5%  [R_0603]  208.87 163.58 270 bottom
PR205  0_0402_5%  [R0402_SHORT]  216.81 168.88 0 bottom
PR206  2.2K_0402_1%  [R_0402]  219.69 164.93 180 bottom
PR207  1K_0402_1%  [R_0402]  218.42 165.79 0 bottom
PR208  1M_0402_5%  [R_0402]  217.05 163.53 0 bottom
PR209  100K_0402_5%  [R_0402]  207.01 171.45 180 top
PR210  0_0402_5%  [R_0402]  205.83 170.57 180 top
PR211  0_0402_5%  [R_0402]  204.32 171.5 0 top
PR212  0_0603_5%  [R0603_SHORT]  202.28 168.51 270 top
PR213  0_0402_5%  [R0402_SHORT]  204.39 173.02 0 bottom
PR214  4.7_0603_5%  [R_0603]  197.56 167.07 270 bottom
PR215  1K_0402_1%  [R_0402]  205.27 171.22 90 bottom
PR216  47K_0402_1%  [R_0402]  223.51 163.5 180 bottom
PR217  47K_0402_1%  [R_0402]  219.45 161.46 0 bottom
PR301  100K_0402_1%  [R_0402]  182.08 174.16 0 top
PR302  220K_0402_1%  [R_0402]  179.35 173.83 0 top
PR303  2.2_0603_5%  [R_0603]  176.25 172.07 270 top
PR304  4.7_0603_5%  [R_0603]  167.72 173.51 270 top
PR305  7.87K_0402_1%  [R_0402]  182.57 165.75 90 top
PR306  5.1_0603_5%  [R_0603]  182.92 175.23 180 top
PR307  10K_0402_1%  [R_0402]  182.56 167.52 0 top
PR308  100K_0402_1%  [R_0402]  183.35 173.29 0 top
PR309  887K_0402_1%  [R_0402]  184.79 172.14 180 top
PR310  0_0402_5%  [R0402_SHORT]  184.39 167.67 0 top
PR311  0_0402_5%  [R_0402]  184.39 166.78 0 top
PR312  0_0402_5%  [R0402_SHORT]  185.25 171.25 180 top
PR313  47K_0402_5%  [R_0402]  185.25 169.48 180 top
PR401  1K_0402_5%  [R_0402]  72.3 53.5 180 bottom
PR402  2_0402_5%  [R_0402]  72.3 52.61 180 bottom
PR403  100_0402_5%  [R_0402]  55.35 59.04 0 bottom
PR404  47_0402_5%  [R_0402]  55.35 59.93 0 bottom
PR405  12K_0402_1%  [R_0402]  56.24 55.68 180 bottom
PR406  10K_0402_1%  [R_0402]  60.28 63.05 180 bottom
PR407  0_0402_5%  [R0402_SHORT]  57.57 62.81 0 bottom
PR408  0_0402_5%  [R0402_SHORT]  58.01 59.76 0 bottom
PR409  75_0402_5%  [R_0402]  56.22 57.77 180 bottom
PR410  51_0402_5%  [R_0402]  58 60.64 0 bottom
PR411  10_0402_5%  [R_0402]  58 58.88 0 bottom
PR412  7.5K_0603_1%  [R_0603]  56.78 56.73 180 bottom
PR413  16.5K_0402_1%  [R_0402]  69.76 66.15 270 bottom
PR414  3.4K_0402_1%  [R_0402]  61.17 50.15 0 bottom
PR415  3.4K_0402_1%  [R_0402]  61.17 51.01 0 bottom
PR416  910_0402_1%  [R_0402]  61.2 51.85 90 bottom
PR417  0_0402_5%  [R0402_SHORT]  62.98 51.53 270 bottom
PR418  61.9K_0402_1%  [R_0402]  63.99 49.74 180 bottom
PR419  2.49K_0402_1%  [R_0402]  57.66 53.68 270 bottom
PR420  53.6K_0402_1%  [R_0402]  57.84 55.07 0 top
PR421  97.6K_0402_1%  [R_0402]  58.58 57.45 180 top
PR422  2.05K_0402_1%  [R_0402]  72.42 56.29 0 bottom
PR423  10_0402_1%  [R_0402]  71.81 57.16 0 bottom
PR424  1.21K_0402_1%  [R_0402]  69.45 61.88 180 top
PR425  26.1K_0402_1%  [R_0402]  71.66 62.57 180 top
PR426  54.9K_0603_1%  [R_0603]  73.74 59.24 270 bottom
PR427  73.2K_0402_1%  [R_0402]  72.63 59.72 270 bottom
PR428  510_0402_1%  [R_0402]  70.77 61.7 270 bottom
PR429  4.75K_0402_1%  [R_0402]  72.37 60.87 270 top
PR430  165K_0402_1%  [R_0402]  71.97 58.91 180 top
PR431  49.9_0402_1%  [R_0402]  71.63 61.68 0 bottom
PR432  12.4K_0402_1%  [R_0402]  70.8 59.09 0 bottom
PR433  2.74K_0402_1%  [R_0402]  67.88 64.22 180 bottom
PR434  2.74K_0402_1%  [R_0402]  68.03 66.15 270 bottom
PR435  0_0402_5%  [R0402_SHORT]  72.41 55.39 0 bottom
PR436  61.9K_0402_1%  [R_0402]  72.32 54.49 0 bottom
PR437  1K_0402_1%  [R_0402]  66.28 66.15 270 bottom
PR438  7.5K_0603_1%  [R_0603]  61.09 66.22 0 bottom
PR439  12K_0402_1%  [R_0402]  60.15 66.43 90 bottom
PR440  1.5K_0402_1%  [R_0402]  64.5 66 0 bottom
PR441  41.2K_0402_1%  [R_0402]  61.96 63.35 0 top
PR442  100K_0402_1%  [R_0402]  60.08 64.85 270 bottom
PR443  24K_0402_1%  [R_0402]  69.35 50.93 90 bottom
PR444  24K_0402_1%  [R_0402]  68.49 50.93 90 bottom
PR445  48.7K_0402_1%  [R_0402]  67.62 50.93 90 bottom
PR446  86.6K_0402_1%  [R_0402]  66.48 50.88 90 bottom
PR447  15.8K_0402_1%  [R_0402]  65.62 50.88 90 bottom
PR448  10K_0402_1%  [R_0402]  64.75 50.88 90 bottom
PR449  2.2_0603_1%  [R_0603]  68.28 70.67 180 bottom
PR450  4.7_0603_5%  [R_0603]  67.29 75.44 270 top
PR451  0_0402_5%  [R0402_SHORT]  72 79.57 180 top
PR452  0_0402_5%  [R0402_SHORT]  72 80.46 180 top
PR453  2.2_0603_1%  [R_0603]  81.64 53.27 270 top
PR454  4.7_0603_5%  [R_0603]  97.39 52.41 90 bottom
PR455  0_0402_5%  [R0402_SHORT]  84.85 62.68 180 top
PR456  0_0402_5%  [R0402_SHORT]  84.85 63.57 180 top
PR457  2.2_0603_1%  [R_0603]  73.51 102.39 0 bottom
PR458  4.7_0603_5%  [R_0603]  67.44 100.57 90 top
PR459  0_0402_5%  [R0402_SHORT]  66.46 105.23 180 top
PR460  0_0402_5%  [R0402_SHORT]  66.46 104.31 180 top
PR601  0_0603_5%  [R0603_SHORT]  111.35 169.79 180 top
PR602  0_0603_5%  [R0603_SHORT]  111.3 172.36 180 top
PR603  0_0402_5%  [R0402_SHORT]  124.25 170.53 180 bottom
PR604  10K_0402_1%  [R_0402]  112.66 166.55 180 bottom
PR605  0_0402_5%  [R0402_SHORT]  111.75 165.65 0 bottom
PR606  0_0402_5%  [R0402_SHORT]  124.91 169.52 180 bottom
PR607  4.7_0603_5%  [R_0603]  92.08 162.39 270 top
PR608  3.65K_0402_1%  [R_0402]  121.83 163.02 0 top
PR609  0_0402_5%  [R0402_SHORT]  125.09 175.15 180 bottom
PR610  0_0402_5%  [R0402_SHORT]  123.06 175.05 180 bottom
PR611  0_0402_5%  [R0402_SHORT]  123.06 171.42 180 bottom
PR612  0_0402_5%  [R_0402]  123.04 172.3 180 bottom
PR613  42.2K_0402_1%  [R_0402]  114.46 164.22 180 bottom
PR614  0_0603_5%  [R0603_SHORT]  112.74 167.71 180 bottom
PR615  0_0402_5%  [R0402_SHORT]  123.06 174.16 180 bottom
PR616  10K_0402_1%  [R_0402]  123.83 164.65 270 bottom
PR617  499_0402_1%  [R_0402]  115.32 164.14 90 bottom
PR618  1_0402_1%  [R_0402]  122.74 163.94 180 bottom
PR619  32.4K_0402_1%  [R_0402]  112.63 165.95 0 top
PR620  0_0603_5%  [R0603_SHORT]  113.24 175.03 180 bottom
PR621  0_0402_5%  [R0402_SHORT]  115.61 163.44 180 top
PR622  10_0402_1%  [R_0402]  114.61 164.32 0 top
PR623  845_0402_1%  [R_0402]  116.21 165.95 180 bottom
PR624  2.7K_0402_1%  [R_0402]  115.3 165.44 180 top
PR625  0_0402_5%  [R0402_SHORT]  114.83 162.56 0 top
PR626  10_0402_1%  [R_0402]  117.33 163.35 0 top
PR627  10K_0402_5%  [R_0402]  117.48 172.88 90 top
PR628  10K_0402_1%  [R_0402]  115.68 173.79 270 top
PR629  10K_0402_1%  [R_0402]  116.57 173.79 270 top
PR630  4.7_0603_5%  [R_0603]  89.67 169.73 90 top
PR631  3.65K_0402_1%  [R_0402]  121.83 163.94 0 top
PR632  10K_0402_1%  [R_0402]  124.72 164.65 270 bottom
PR633  2.61K_0402_1%  [R_0402]  120.83 162.34 180 bottom
PR634  11K_0402_1%  [R_0402]  120.07 164.09 180 bottom
PR635  649_0402_1%  [R_0402]  119.16 165.87 270 bottom
PR636  1_0402_1%  [R_0402]  122.75 163.09 270 bottom
PR637  0_0402_5%  [R_0402]  118.37 172.88 90 top
PR638  100K_0402_1%  [R_0402]  119.97 174.05 270 top
PR639  100_0402_1%  [R_0402]  120.05 164.14 270 top
PR640  100K_0402_1%  [R_0402]  120.07 174.96 180 bottom
PR641  27.4K_0402_1%  [R_0402]  120.99 168.61 0 bottom
PR642  130K_0402  [R_0402]  123.73 168.64 270 bottom
PR643  10.7K_0402_1%  [R_0402]  121.98 167.72 0 bottom
PR644  0_0402_5%  [R_0402]  123.04 173.26 180 bottom
PR701  0_0402_5%  [R0402_SHORT]  147.36 166.39 270 bottom
PR702  210K_0402_1%  [R_0402]  151.62 166.07 180 bottom
PR703  210K_0402_1%  [R_0402]  152.19 166.97 180 bottom
PR704  100K_0402_1%  [R_0402]  146.47 166.39 270 bottom
PR705  0_0402_5%  [R_0402]  147.63 169.45 0 top
PR706  0_0402_5%  [R_0402]  154.13 169.58 180 bottom
PR707  0_0603_5%  [R0603_SHORT]  146.16 170.43 180 top
PR708  4.7_0603_5%  [R_0603]  144.96 172.9 180 top
PR801  0_0402_5%  [R0402_SHORT]  185.08 174.57 90 bottom
PR802  1M_0402_5%  [R_0402]  188.75 175.17 180 top
PR803  4.7_0603_5%  [R_0603]  189.23 169.99 180 top
PR804  20K_0402_1%  [R_0402]  193.06 173.4 180 bottom
PR805  10K_0402_1%  [R_0402]  193.72 175.56 0 bottom
PRT1  540_0402NEW_30%  [R_0402]  236.97 115.67 90 bottom
PRT2  540_0402NEW_30%  [R_0402]  104.55 157.89 0 bottom
PRT3  540_0402NEW_30%  [R_0402]  168.56 166.86 180 bottom
PRT4  540_0402NEW_30%  [R_0402]  65.69 98.61 0 bottom
PRT5  540_0402NEW_30%  [R_0402]  68.41 68.59 90 bottom
PRT6  540_0402NEW_30%  [R_0402]  79.46 53.12 180 bottom
PRT7  100K_0402_1%_NCP15WF104F03RC  [R_0402]  107.98 115.48 0 top
PRT401  MURAT_NCP15WF104F03RC  [R_0402-TH]  68.74 85.17 0 bottom
PRT402  MURAT_NCP15WF104F03RC  [R_0402-TH]  62.09 71.38 0 bottom
PRT403  MURAT_NCP15WM224J03RC  [R_0402-TH]  85.53 65.28 90 bottom
PRT404  MURAT_NCP15WF104F03RC  [R_0402-TH]  76.53 54.52 90 bottom
PRT405  MURAT_NCP15WF104F03RC  [R_0402-TH]  69.63 110.34 180 bottom
PRT601  10K_0402_NTC  [R_0402]  88.98 157.33 180 bottom
PRT602  470K_0402NEW_3%  [R_0402]  103.59 175.27 180 bottom
PU1  -  [G718TM1U_SOT23-8]  223.68 168.28 270 top
PU101  BQ24780SRUYR  [BQ24780RUYR_QFN24_4X4]  220.61 109.66 180 bottom
PU201  -  [SYX198BQNC_QFN10_3X3]  214.48 165.64 180 bottom
PU202  -  [SYX198CQNC_QFN10_3X3]  202.87 171.01 180 bottom
PU301  RT8231AGQW  [RT8231AGQW_WQFN20_3X3]  179.76 168.79 90 top
PU401  -  [NCP81208MNTXG_QFN48_6X6]  67.32 60.36 180 bottom
PU402  -  [NCP81253MNTBG_DFN8_2X2]  65.95 70.29 180 bottom
PU403  NCP81151MNTBG_DFN8_2X2  [NCP81253MNTBG_DFN8_2X2]  82.79 50.32 0 top
PU404  -  [NCP81253MNTBG_DFN8_2X2]  75.93 100.9 270 bottom
PU601  -  [ISL62771HRTZ_TQFN40_5X5]  119.29 173.11 180 bottom
PU701  TPS51367RVER  [TPS51367RVER_QFN28_3P5X4P5]  147.89 168.76 90 bottom
PU801  RT8068AZQW  [RT8068AZQW_WDFN10_3X3]  187.78 172.01 90 bottom
Q1  -  [MMST3904-7-F_SOT323-3]  163.48 113.35 180 top
Q2  -  [MMST3904-7-F_SOT323-3]  3.03 132.87 180 top
Q4  -  [2N7002KW_SOT323-3]  275.95 112.08 180 top
Q22  -  [AO3401A_SOT23-3]  278.34 44.48 90 bottom
Q23  -  [AO4430L_SO8]  141.12 157.51 90 top
Q24  -  [2N7002KDWH_SOT363-6]  146.75 161.77 270 top
Q26  2N7002WT1G_1N_SC-70-3  [2N7002KW_SOT323-3]  271 131.19 0 top
Q27  -  [AO3413_SOT23-3]  266.15 132.24 270 top
Q28  -  [2N7002KDWH_SOT363-6]  179.36 144.17 180 top
Q29  -  [AO3413_SOT23-3]  117.72 159.3 270 top
QC1  -  [2N7002KDWH_SOT363-6]  105.99 149.02 270 top
QC2  -  [2N7002KDWH_SOT363-6]  102.05 149.4 270 top
QC3  -  [2N7002KDWH_SOT363-6]  86.25 97.91 90 top
QD1  -  [DTC115TMT2L_VMT3]  172.97 133.9 0 top
QE1  2N7002WT1G_1N_SC-70-3  [2N7002KW_SOT323-3]  198.27 122.84 90 top
QG1  -  [AO3413_SOT23-3]  173.25 109.55 0 top
QL2  -  [AO3413_SOT23-3]  246.49 95.94 0 bottom
QL3  2N7002WT1G_1N_SC-70-3  [2N7002KW_SOT323-3]  243.86 101 270 bottom
QV2  -  [2N7002KDWH_SOT363-6]  85.84 152.07 180 bottom
QV3  -  [MMST3904-7-F_SOT323-3]  55.86 130.17 0 bottom
QV4  -  [2N7002KW_SOT323-3]  72.75 151.2 0 bottom
QV5  -  [AO3413_SOT23-3]  73.77 162.11 180 top
QV7  -  [2N7002KW_SOT323-3]  84.84 142.23 180 top
QV8  -  [2N7002KDWH_SOT363-6]  80.99 154.1 270 bottom
QV9  -  [AO4430L_SO8]  46.41 130.13 270 bottom
QV10  -  [2N7002KDWH_SOT363-6]  42.92 133.9 270 bottom
QV11  -  [2N7002KW_SOT323-3]  53.09 129.85 180 bottom
QV13  -  [NTJD5121NT1G_SC88-6]  183.89 107.11 0 top
R3  10K_0402_5%  [R_0402]  45.57 122.97 270 top
R4  2.2K_0402_5%  [R_0402]  282.1 53.27 0 bottom
R5  2.2K_0402_5%  [R_0402]  282.1 54.16 0 bottom
R17  0_0402_5%  [R0402_SHORT]  65.46 118.21 225 bottom
R18  100K_0402_5%  [R_0402]  66.66 118.02 45 bottom
R19  0_0402_5%  [R_0402]  59.85 124.85 225 bottom
R20  0_0402_5%  [R_0402]  59.21 125.48 225 bottom
R21  100K_0402_5%  [R_0402]  60.63 115.04 225 bottom
R22  0_0402_5%  [R0402_SHORT]  59.99 115.67 225 bottom
R24  0_0805_5%  [R0805_SHORT]  64.46 111.89 225 bottom
R25  2.2K_0402_1%  [R_0402]  60.48 119.03 225 bottom
R26  100K_0402_5%  [R_0402]  56.3 118.07 45 bottom
R27  0_0402_5%  [R_0402]  201.89 97 180 top
R28  0_0402_5%  [R_0402]  201.73 94.77 180 top
R29  0_0402_5%  [R_0402]  211.59 95.13 180 top
R30  4.99K_0402_1%  [R_0402]  211.77 91.6 90 top
R31  0_0402_5%  [R_0402]  201.71 93.45 180 top
R32  0_0402_5%  [R_0402]  211.61 93.83 180 top
R33  0_0402_5%  [R_0402]  201.91 95.71 180 top
R34  0_0402_5%  [R_0402]  217.43 92.44 270 top
R35  4.7K_0402_5%  [R_0402]  204.83 99.52 90 top
R36  4.7K_0402_5%  [R_0402]  203.82 99.52 90 top
R37  4.7K_0402_5%  [R_0402]  202.8 99.52 90 top
R38  4.7K_0402_5%  [R_0402]  206.86 99.52 90 top
R39  4.7K_0402_5%  [R_0402]  205.85 99.52 90 top
R40  4.7K_0402_5%  [R_0402]  206.99 91.42 270 top
R41  4.7K_0402_5%  [R_0402]  206.05 91.09 180 top
R42  4.7K_0402_5%  [R_0402]  210.32 91.42 270 top
R43  4.7K_0402_5%  [R_0402]  207.88 91.42 270 top
R44  0_0402_5%  [R_0402]  219.03 97.44 180 top
R45  4.99K_0402_1%  [R_0402]  228.63 92.95 180 top
R46  0_0402_5%  [R_0402]  229.55 95.18 180 top
R47  0_0402_5%  [R_0402]  219.54 92.45 270 top
R48  0_0402_5%  [R_0402]  229.55 93.83 180 top
R49  4.7K_0402_5%  [R_0402]  222.59 99.47 90 top
R50  4.7K_0402_5%  [R_0402]  219.92 99.47 90 top
R51  4.7K_0402_5%  [R_0402]  224.36 99.47 90 top
R52  4.7K_0402_5%  [R_0402]  219.03 99.47 90 top
R53  4.7K_0402_5%  [R_0402]  223.48 99.47 90 top
R54  4.7K_0402_5%  [R_0402]  222.84 91.37 270 top
R55  4.7K_0402_5%  [R_0402]  221.95 91.37 270 top
R56  4.7K_0402_5%  [R_0402]  226.27 91.5 270 top
R57  4.7K_0402_5%  [R_0402]  223.73 91.37 270 top
R58  0_0603_5%  [R0603_SHORT]  126.3 70.34 270 bottom
R59  4.7K_0402_5%  [R_0402]  142.63 61.98 90 top
R60  4.7K_0402_5%  [R_0402]  143.52 61.98 90 top
R61  4.7K_0402_5%  [R_0402]  119.74 70.34 270 bottom
R62  0_0402_5%  [R_0402]  219.06 96.12 180 top
R63  4.7K_0402_5%  [R_0402]  127.63 70.1 270 bottom
R64  0_0402_5%  [R0402_SHORT]  119.82 68.49 180 bottom
R65  4.7K_0402_5%  [R_0402]  128.52 70.1 270 bottom
R66  0_0402_5%  [R_0402]  121.6 69.37 180 bottom
R67  100K_0402_5%  [R_0402]  122.66 70.34 270 bottom
R68  0_0603_5%  [R0603_SHORT]  54.98 50.21 180 top
R69  100K_0402_5%  [R_0402]  271.46 134.02 180 top
R70  0_0402_5%  [R0402_SHORT]  189.16 74.07 180 top
R71  100K_0402_5%  [R_0402]  269.58 149.28 0 top
R72  0_0402_5%  [R_0402]  210.67 95.13 180 top
R74  0_0402_5%  [R_0402]  210.7 93.83 180 top
R75  0_0402_5%  [R_0402]  228.63 95.18 180 top
R76  0_0402_5%  [R_0402]  228.63 93.83 180 top
R83  100K_0402_5%  [R_0402]  276.28 113.44 180 top
R84  2.2K_0402_1%  [R_0402]  281.06 28.18 270 top
R88  100K_0402_5%  [R_0402]  276.6 120.32 0 bottom
R89  100_0402_1%  [R_0402]  254.62 151.11 270 top
R90  100_0402_1%  [R_0402]  257.03 153.27 270 top
R91  100K_0402_5%  [R_0402]  255.51 152.36 90 top
R93  100K_0402_5%  [R_0402]  277.49 118.41 90 bottom
R94  0_0805_5%  [R_0805]  247.09 147.71 0 top
R95  0_0805_5%  [R_0805]  247.09 150.12 0 top
R98  0_0402_5%  [R_0402]  280.83 120.81 0 top
R103  0_0402_5%  [R_0402]  274.86 115.22 0 top
R104  0_0402_5%  [R_0402]  274.86 114.33 0 top
R105  1M_0402_5%  [R_0402]  279.09 113.86 180 top
R106  100K_0402_5%  [R_0402]  278.54 112.3 0 top
R107  100K_0402_5%  [R_0402]  278.54 111.03 0 top
R108  0_0402_5%  [R0402_SHORT]  118.85 70.34 270 bottom
R111  300_0402_5%  [R_0402]  165.28 73.82 180 top
R112  1K_0603_5%  [R_0603]  233.79 173.26 0 bottom
R113  100K_0402_5%  [R_0402]  252.93 152.07 270 top
R114  0_0402_5%  [R_0402]  274.3 122.31 270 top
R115  0_0402_5%  [R_0402]  273.41 122.31 270 top
R116  0_0402_5%  [R_0402]  277.91 116.75 0 top
R117  0_0402_5%  [R_0402]  277.91 115.86 0 top
R118  20K_0402_1%  [R_0402]  140.04 67.55 0 top
R120  20K_0402_1%  [R_0402]  140.04 68.43 0 top
R121  0_0402_5%  [R_0402]  136.5 63.86 270 top
R122  0_0402_5%  [R_0402]  137.44 63.86 270 top
R150  0_0402_5%  [R_0402]  258.81 153.27 270 top
R151  0_0402_5%  [R_0402]  255.51 150.2 90 top
R156  100K_0402_5%  [R_0402]  181.68 143.68 180 top
R157  100K_0402_5%  [R_0402]  181.68 142.67 180 top
R159  47_0603_5%  [R_0603]  175.5 144.18 0 top
R239  1K_0402_5%  [R_0402]  257.92 152.36 90 top
R240  0_0402_5%  [R_0402]  271.09 120.95 180 top
R241  0_0402_5%  [R_0402]  271.09 119.55 180 top
R242  0_0402_5%  [R_0402]  270.15 123.76 0 top
R243  0_0402_5%  [R_0402]  270.17 122.22 0 top
R244  4.7K_0402_5%  [R_0402]  268.6 125.7 90 top
R245  4.7K_0402_5%  [R_0402]  265.93 125.7 90 top
R246  4.7K_0402_5%  [R_0402]  267.71 125.7 90 top
R247  4.7K_0402_5%  [R_0402]  266.9 117.85 270 top
R248  4.7K_0402_5%  [R_0402]  268.98 117.85 270 top
R249  4.7K_0402_5%  [R_0402]  266.82 125.7 90 top
R250  4.7K_0402_5%  [R_0402]  265.04 125.7 90 top
R251  4.7K_0402_5%  [R_0402]  267.96 117.85 270 top
R252  4.7K_0402_5%  [R_0402]  271.14 117.85 270 top
R253  0_0402_5%  [R_0402]  261.05 123.62 180 top
R254  0_0402_5%  [R_0402]  261.05 122.22 180 top
R255  0_0402_5%  [R_0402]  271.98 123.74 180 top
R256  0_0402_5%  [R_0402]  271.98 122.22 180 top
R257  0_0402_5%  [R_0402]  271.06 120.95 0 top
R258  0_0402_5%  [R_0402]  271.06 119.55 0 top
R259  0_0402_5%  [R_0402]  260.14 121.33 0 top
R260  0_0402_5%  [R_0402]  260.14 119.93 0 top
R261  10K_0402_5%  [R_0402]  131.13 155.37 180 top
R263  33_0402_5%  [R_0402]  133.53 160.05 180 top
R264  33_0402_5%  [R_0402]  133.53 163.48 180 top
R265  33_0402_5%  [R_0402]  133.53 159.16 180 top
R266  33_0402_5%  [R_0402]  133.53 158.27 180 top
R267  10K_0402_5%  [R_0402]  130.54 164.45 270 top
R268  10K_0402_5%  [R_0402]  123.23 160.6 270 top
R269  0_0402_5%  [R0402_SHORT]  241.42 153.41 270 top
R270  0_0402_5%  [R0402_SHORT]  242.44 153.41 270 top
R271  33_0402_5%  [R_0402]  130.22 153.59 0 top
R272  0_0805_5%  [R0805_SHORT]  87.34 93.82 90 top
R273  10K_0402_5%  [R_0402]  115.97 159.79 270 top
R722  10K_0402_1%  [R_0402]  76.55 114.68 180 top
R9446  10K_0402_5%  [R_0402]  148.2 157.91 90 top
R9447  0_0402_5%  [R0402_SHORT]  144.95 161.39 90 top
R9448  100K_0402_5%  [R_0402]  148.4 164.51 180 top
R9449  0_0402_5%  [R0402_SHORT]  270.54 135.03 0 top
R9450  47K_0402_5%  [R_0402]  271.84 129.83 180 top
R9451  10K_0402_5%  [R_0402]  270.06 129.83 180 top
R9455  4.99K_0402_1%  [R_0402]  272.03 116.94 90 top
R9456  100_0402_5%  [R_0402]  118.33 156.31 0 top
R9457  4.7K_0402_5%  [R_0402]  264.56 123.85 90 bottom
R9458  4.7K_0402_5%  [R_0402]  265.58 123.85 0 bottom
R9459  4.7K_0402_5%  [R_0402]  267.45 114.7 90 top
R9460  4.7K_0402_5%  [R_0402]  268.42 114.7 90 top
R9461  4.7K_0402_5%  [R_0402]  202.48 102.71 0 top
R9462  4.7K_0402_5%  [R_0402]  205.22 102.71 180 top
R9463  4.7K_0402_5%  [R_0402]  204.13 92.45 0 bottom
R9464  4.7K_0402_5%  [R_0402]  207.41 93.29 270 bottom
R9465  4.7K_0402_5%  [R_0402]  221.76 94.05 270 bottom
R9466  4.7K_0402_5%  [R_0402]  223 93.62 270 bottom
R9467  4.7K_0402_5%  [R_0402]  220.79 100.38 270 top
R9468  4.7K_0402_5%  [R_0402]  221.68 100.38 270 top
R9492  0_0402_5%  [R0402_SHORT]  76.47 119.68 180 top
R9494  10K_0402_5%  [R_0402]  76.09 120.57 0 top
RA1  0_0805_5%  [R0805_SHORT]  177.79 54.62 180 top
RA2  0_0805_5%  [R_0805]  179.72 58.76 180 top
RA3  0_0805_5%  [R_0805]  178.71 60.97 0 top
RA4  0_0805_5%  [R0805_SHORT]  180.41 62.69 180 top
RA5  33_0402_5%  [R_0402]  192.23 56.62 180 top
RA6  0_0805_5%  [R0805_SHORT]  181.05 54.64 180 top
RA7  33_0402_5%  [R_0402]  189.34 52.15 90 top
RA8  BLM18PG221SN1D_2P  [MURAT_BLM18PG121SN1D_2P]  188.05 61.5 90 top
RA9  BLM18PG221SN1D_2P  [MURAT_BLM18PG121SN1D_2P]  190.19 61.65 90 top
RA10  BLM18PG221SN1D_2P  [MURAT_BLM18PG121SN1D_2P]  186.84 61.5 90 top
RA11  33_0402_5%  [R_0402]  193.28 63.16 270 top
RA12  BLM18PG221SN1D_2P  [MURAT_BLM18PG121SN1D_2P]  184.4 61.47 90 top
RA13  10K_0402_5%  [R_0402]  194.16 63.16 270 top
RA14  100_0402_5%  [R_0402]  181.85 53.19 270 top
RA15  100_0402_5%  [R_0402]  183.75 53.19 270 top
RA16  3K_0402_5%  [R_0402]  188.07 50.38 90 top
RA17  75_0402_5%  [R_0402]  183.62 51.04 270 top
RA18  5.11K_0402_1%  [R_0402]  190.99 49.46 270 top
RA19  100_0402_5%  [R_0402]  184.77 53.19 270 top
RA20  20K_0402_1%  [R_0402]  188.97 48.61 90 top
RA21  39.2K_0402_1%  [R_0402]  189.86 48.61 90 top
RA22  3K_0402_5%  [R_0402]  187.43 52.28 90 top
RA23  75_0402_5%  [R_0402]  187.18 51.29 270 top
RA24  100_0402_5%  [R_0402]  186.04 53.19 270 top
RA25  0_0402_5%  [R_0402]  194.6 58.78 180 top
RA27  0_0402_5%  [R0402_SHORT]  194.6 57.39 180 top
RA28  0_0402_5%  [R0402_SHORT]  191.62 52.15 90 top
RA29  47K_0402_5%  [R_0402]  183.45 69.12 180 bottom
RA30  0_0805_5%  [R0805_SHORT]  177.06 61.88 180 top
RC1  2.2K_0402_5%  [R_0402]  101.58 143.62 270 top
RC2  2.2K_0402_5%  [R_0402]  100.69 143.62 270 top
RC3  51_0402_1%  [R_0402]  89.48 104.19 180 bottom
RC4  51_0402_1%  [R_0402]  89.48 102.46 180 bottom
RC5  499_0402_1%  [R_0402]  90.47 98.52 0 top
RC6  51_0402_1%  [R_0402]  89.43 106.85 180 bottom
RC8  121_0402_1%  [R_0402]  117.09 125.88 180 top
RC9  80.6_0402_1%  [R_0402]  118.59 125.57 0 top
RC10  100_0402_1%  [R_0402]  119.23 127.34 270 top
RC11  0_0402_5%  [R0402_SHORT]  137.9 146.08 180 top
RC12  20K_0402_5%  [R_0402]  133.65 135.4 0 top
RC13  10M_0402_5%  [R_0402]  123.48 143.85 90 top
RC14  20K_0402_5%  [R_0402]  133.64 136.3 0 top
RC16  1M_0402_5%  [R_0402]  132.53 144.67 180 top
RC19  220_0402_1%  [R_0402]  91.37 98.97 180 bottom
RC20  56_0402_1%  [R_0402]  88.96 98.08 180 bottom
RC21  0_0402_5%  [R0402_SHORT]  138.16 114.51 90 top
RC24  22_0402_5%  [R_0402]  128.52 134.56 90 top
RC26  100K_0402_5%  [R_0402]  75.5 122.33 180 top
RC27  10K_0402_5%  [R_0402]  138.28 142.86 270 top
RC29  10K_0402_5%  [R_0402]  128.25 147.73 270 top
RC30  1M_0402_5%  [R_0402]  92.06 116.11 270 bottom
RC31  51_0402_1%  [R_0402]  89.48 105.96 180 bottom
RC32  10K_0402_5%  [R_0402]  129.27 147.73 270 top
RC34  51_0402_1%  [R_0402]  89.48 105.08 180 bottom
RC40  0_0402_5%  [R0402_SHORT]  91.43 133.83 90 bottom
RC41  0_0402_5%  [R0402_SHORT]  142.09 128.56 0 top
RC47  0_0402_5%  [R_0402]  129.71 133.73 0 top
RC48  33_0402_5%  [R_0402]  73.9 118.73 270 top
RC52  8.2K_0402_5%  [R_0402]  129.71 134.62 0 top
RC53  1K_0402_1%  [R_0402]  90.46 101.25 0 bottom
RC54  0_0402_5%  [R_0402]  88.04 101.25 0 bottom
